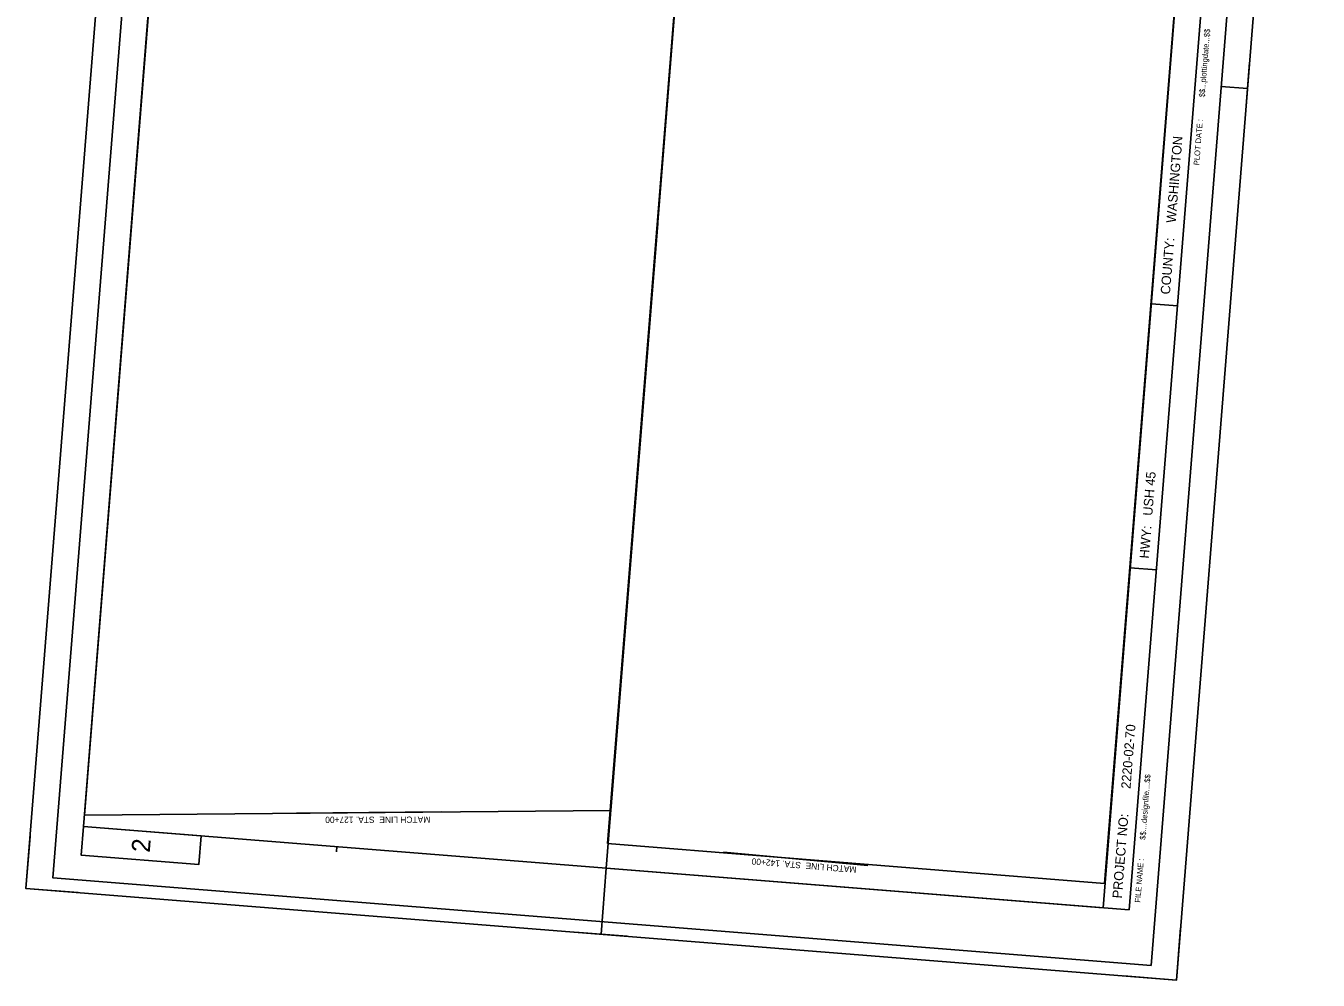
# Model space of a CAD drawing. Extents: x 360843 to 362075, y 137204 to 138986.
# Drawn here: x 360843 to 362075, y 137204 to 138113 of the extents above; entities that cross this region are included whole.
import ezdxf

# ---------------------------------------------------------------- set-up
doc = ezdxf.new("R2010")
doc.units = 0
for name, color, linetype in [('Default', 7, 'Continuous'), ('P_SHTIDX_3 [KAPUR_CADDS_LEVELS]', 7, 'Continuous'), ('P_SHTIDX_4 [KAPUR_CADDS_LEVELS]', 7, 'Continuous'), ('P_TXT_Plan 1 [KAPUR_CADDS_LEVELS]', 7, 'Continuous'), ('P_TXT_Plan 3 [KAPUR_CADDS_LEVELS]', 7, 'Continuous'), ('P_TXT_Plan 4 [KAPUR_CADDS_LEVELS]', 7, 'Continuous'), ('P_TXT_Plan 4_TEXT [KAPUR_CADDS_LEVELS]', 7, 'Continuous'), ('PLT_Sheet_Info', 7, 'Continuous')]:
    doc.layers.add(name, color=color, linetype=linetype)

msp = doc.modelspace()

# ---------------------------------------------------------------- linework, layer by layer
at = {"layer": 'Default'}
for points in [[(360898.9, 137361.2), (361400.8, 137365.7), (361517.7, 138830.6), (361020.9, 138890.2)], [(360898.9, 137361.2), (361400.8, 137365.7), (361517.7, 138830.6), (361020.9, 138890.2)], [(360898.9, 137361.2), (361400.8, 137365.7), (361517.7, 138830.6), (361020.9, 138890.2)], [(360898.9, 137361.2), (361400.8, 137365.7), (361517.7, 138830.6), (361020.9, 138890.2)], [(360898.9, 137361.2), (361400.8, 137365.7), (361517.7, 138830.6), (361020.9, 138890.2)], [(360898.9, 137361.2), (361400.8, 137365.7), (361517.7, 138830.6), (361020.9, 138890.2)], [(360898.9, 137361.2), (361400.8, 137365.7), (361517.7, 138830.6), (361020.9, 138890.2)], [(360898.9, 137361.2), (361400.8, 137365.7), (361517.7, 138830.6), (361020.9, 138890.2)], [(360898.9, 137361.2), (361400.8, 137365.7), (361517.7, 138830.6), (361020.9, 138890.2)], [(361397.4, 137334.1), (361871.2, 137295.9), (361991.4, 138795.1), (361517.4, 138826.9)], [(361397.4, 137334.1), (361871.2, 137295.9), (361991.4, 138795.1), (361517.4, 138826.9)], [(361397.4, 137334.1), (361871.2, 137295.9), (361991.4, 138795.1), (361517.4, 138826.9)], [(361397.4, 137334.1), (361871.2, 137295.9), (361991.4, 138795.1), (361517.4, 138826.9)], [(361397.4, 137334.1), (361871.2, 137295.9), (361991.4, 138795.1), (361517.4, 138826.9)], [(361397.4, 137334.1), (361871.2, 137295.9), (361991.4, 138795.1), (361517.4, 138826.9)], [(361397.4, 137334.1), (361871.2, 137295.9), (361991.4, 138795.1), (361517.4, 138826.9)], [(361397.4, 137334.1), (361871.2, 137295.9), (361991.4, 138795.1), (361517.4, 138826.9)], [(361397.4, 137334.1), (361871.2, 137295.9), (361991.4, 138795.1), (361517.4, 138826.9)]]:
    msp.add_lwpolyline(points, close=True, dxfattribs=at)
at = {"layer": 'P_SHTIDX_3 [KAPUR_CADDS_LEVELS]'}
msp.add_lwpolyline([(360843.1, 137291.4), (360978.4, 138986), (362074.9, 138898.5), (361939.7, 137203.9), (360843.1, 137291.4)], dxfattribs=at)
at = {"layer": 'P_SHTIDX_4 [KAPUR_CADDS_LEVELS]'}
for p, q in [((360898, 137350.5), (361023.3, 138920.5)), ((361869.9, 137272.9), (361995.2, 138843)), ((361894.8, 137271), (362020.1, 138841)), ((362005.5, 138028.8), (362009.4, 138078.6)), ((362007.5, 138053.7), (361982.5, 138055.7)), ((361396.4, 137310.7), (361445.4, 137924.9)), ((361940.8, 137846.6), (361915.9, 137848.6)), ((361920.7, 137594.9), (361895.8, 137596.9)), ((361894.8, 137271), (360898, 137350.5)), ((360843.1, 137291.4), (360847.1, 137341.3)), ((361399.4, 137348.1), (361399.4, 137348.1)), ((361139.7, 137331.2), (361139.3, 137326.2)), ((361391.4, 137247.7), (361396.4, 137310.7)), ((360893, 137287.4), (360843.1, 137291.4)), ((361939.7, 137203.9), (361943.6, 137253.8)), ((361416.3, 137245.7), (361366.5, 137249.7)), ((361939.7, 137203.9), (361889.8, 137207.9))]:
    msp.add_line(p, q, dxfattribs=at)
msp.add_lwpolyline([(360898, 137350.5), (360895.8, 137323.1), (361008, 137314.1), (361010.2, 137341.6)], close=True, dxfattribs=at)
at = {"layer": 'P_TXT_Plan 1 [KAPUR_CADDS_LEVELS]'}
msp.add_line((361396.4, 137310.7), (361521.7, 138880.7), dxfattribs=at)
msp.add_lwpolyline([(361396.4, 137310.7), (361869.9, 137272.9)], dxfattribs=at)
at = {"layer": 'P_TXT_Plan 4 [KAPUR_CADDS_LEVELS]'}
for p, q in [((361101, 137363), (361239.1, 137364.2)), ((361508.2, 137325.9), (361645.7, 137313.2))]:
    msp.add_line(p, q, dxfattribs=at)
at = {"layer": 'P_TXT_Plan 4_TEXT [KAPUR_CADDS_LEVELS]'}
msp.add_lwpolyline([(360843.1, 137291.4), (360978.4, 138986), (362074.9, 138898.5), (361939.7, 137203.9)], close=True, dxfattribs=at)
at = {"layer": 'PLT_Sheet_Info'}
for points in [[(361939.7, 137203.9), (362074.9, 138898.5), (360978.4, 138986), (360843.1, 137291.4)], [(361915.7, 137217.9), (362047.3, 138867.6), (361000.7, 138951.2), (360869, 137301.4)]]:
    msp.add_lwpolyline(points, close=True, dxfattribs=at)

# ---------------------------------------------------------------- texts
at = {"layer": 'P_SHTIDX_4 [KAPUR_CADDS_LEVELS]'}
for s, height, p in [('$$...plottingdate...$$', 5.4, (361966.7, 138045.2)), ('PLOT DATE :', 5.4, (361961.5, 137980.4)), (' WASHINGTON', 9, (361938.8, 137922)), ('COUNTY:', 9, (361933.6, 137857.2)), (' USH 45', 9, (361916.5, 137642.9)), ('HWY:', 9, (361913.5, 137605.5)), (' 2220-02-70', 9, (361895.7, 137382.7)), ('$$....designfile....$$', 5.4, (361910.2, 137337.5)), ('PROJECT NO:', 9, (361887.7, 137281.6)), ('2', 17.5, (360961.2, 137325.1)), ('FILE NAME :', 5.4, (361905.4, 137277.6))]:
    msp.add_text(s, height=height, rotation=85.4379, dxfattribs=at).set_placement(p)
at = {"layer": 'P_TXT_Plan 3 [KAPUR_CADDS_LEVELS]'}
for s, rotation, p in [('MATCH LINE  STA. 127+00', 180.1019, (361228.6, 137359.9)), ('MATCH LINE  STA. 142+00', 175.3491, (361635, 137312.1))]:
    msp.add_text(s, height=6, rotation=rotation, dxfattribs=at).set_placement(p)

doc.saveas('drawing.dxf')
